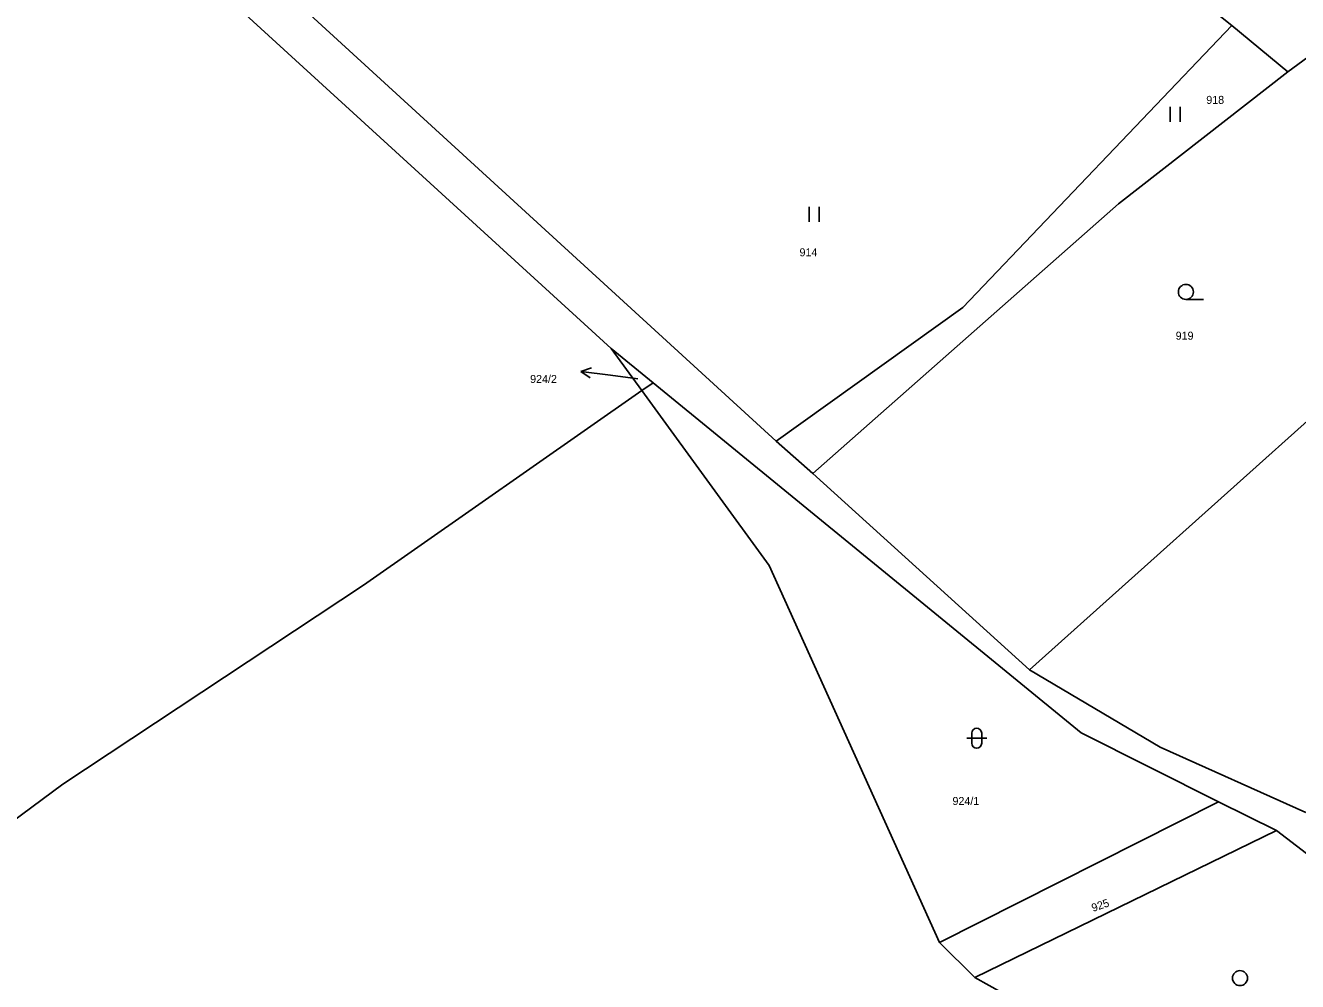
# Model space of a CAD drawing. Extents: x -719706 to -718922, y -950351 to -949651.
# Drawn here: x -719188 to -719060.8, y -950096.9 to -950001.3 of the extents above; entities that cross this region are included whole.
import ezdxf

# ---------------------------------------------------------------- set-up
doc = ezdxf.new("R2010")
doc.units = 0
doc.layers.add('Doplňující texty', color=7, linetype='Continuous')

msp = doc.modelspace()

# ---------------------------------------------------------------- linework, layer by layer
at = {"layer": 'Doplňující texty'}
for p, q in [((-719186, -949981.9), (-719129.44, -950033.6)), ((-719112.95, -950042.88), (-719176.68, -949984.54)), ((-719061.8, -950005.94), (-719049.14, -949996.64)), ((-719067.4, -950001.3), (-719061.8, -950005.94)), ((-719073.57, -950010.94), (-719073.57, -950009.44)), ((-719072.57, -950010.94), (-719072.57, -950009.44)), ((-719109.65, -950020.92), (-719109.65, -950019.42)), ((-719108.65, -950020.92), (-719108.65, -950019.42)), ((-719072, -950028.69), (-719070.25, -950028.69)), ((-719129.44, -950033.6), (-719126.38, -950037.81)), ((-719129.44, -950033.6), (-719125.26, -950037.02)), ((-719132.49, -950035.9), (-719131.43, -950035.53)), ((-719087.64, -950065.74), (-719052.65, -950034.37)), ((-719129.51, -950036.27), (-719132.49, -950035.9)), ((-719132.49, -950035.9), (-719131.56, -950036.52)), ((-719126.78, -950036.62), (-719129.51, -950036.27)), ((-719125.26, -950037.02), (-719126.38, -950037.81)), ((-719109.3, -950046.1), (-719112.95, -950042.88)), ((-719087.64, -950065.74), (-719109.3, -950046.1)), ((-719093.41, -950072.07), (-719093.41, -950073.07)), ((-719092.41, -950073.07), (-719092.41, -950072.07)), ((-719093.91, -950072.57), (-719091.91, -950072.57)), ((-719096.64, -950092.99), (-719068.74, -950078.94)), ((-719068.74, -950078.94), (-719062.94, -950081.81)), ((-719093.08, -950096.5), (-719062.94, -950081.81)), ((-719062.94, -950081.81), (-719042.32, -950097.63)), ((-719096.64, -950092.99), (-719093.08, -950096.5))]:
    msp.add_line(p, q, dxfattribs=at)
for points in [[(-719067.4, -950001.3), (-719074.22, -949995.83), (-719079.48, -949990.11), (-719085.79, -949984.81), (-719104.53, -949962.42)], [(-719112.95, -950042.88), (-719094.29, -950029.5), (-719067.4, -950001.3)], [(-719109.3, -950046.1), (-719078.75, -950019.12), (-719061.8, -950005.94)], [(-719126.38, -950037.81), (-719154.2, -950057.28), (-719184.27, -950077.15), (-719202.89, -950090.97), (-719243.68, -950122.31), (-719293.03, -950169.31), (-719360.2, -950220.1), (-719387.28, -950232.05), (-719421.72, -950250.15), (-719452.59, -950265.64), (-719506.49, -950290.59), (-719587.31, -950333.84), (-719619.07, -950350.8)], [(-719126.38, -950037.81), (-719125.32, -950039.27), (-719113.67, -950055.31), (-719096.64, -950092.99)], [(-719125.26, -950037.02), (-719082.47, -950072.02), (-719068.74, -950078.94)], [(-719060, -950080), (-719074.56, -950073.47), (-719087.64, -950065.74)], [(-719065.85, -950112.77), (-719073.04, -950107.68), (-719093.08, -950096.5)]]:
    msp.add_lwpolyline(points, dxfattribs=at)
for centre in [(-719072, -950027.94), (-719066.59, -950096.56)]:
    msp.add_circle(centre, 0.75, dxfattribs=at)
for centre, start, end in [((-719092.91, -950072.07), 0, 180), ((-719092.91, -950073.07), 180, 359.9879)]:
    msp.add_arc(centre, 0.5, start, end, dxfattribs=at)

# ---------------------------------------------------------------- texts
for s, p in [('918', (-719069.96, -950009.14)), ('914', (-719110.62, -950024.38)), ('919', (-719073.02, -950032.72)), ('924/2', (-719137.55, -950037.05)), ('924/1', (-719095.33, -950079.25))]:
    msp.add_text(s, height=0.8, dxfattribs=at).set_placement(p)
msp.add_text('925', height=0.8, rotation=19, dxfattribs=at).set_placement((-719081.27, -950089.94))

doc.saveas('drawing.dxf')
